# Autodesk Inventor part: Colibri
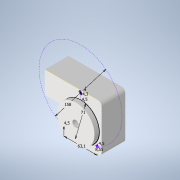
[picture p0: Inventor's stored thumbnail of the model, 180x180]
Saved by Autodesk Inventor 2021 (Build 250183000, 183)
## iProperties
Created: 2021-03
Part Number: Colibri
Material: Genérico
Document SubType Name: Modeling
Designer: ATOUZA
Density: 1 g/cm^3
Appearance: Valor por defecto
Author: ATOUZA
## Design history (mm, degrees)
sketch "Boceto1"
  geometry: L1 (-36.9, -38.8)-(40.1, -38.8); L2 (-67.9, 51.2)-(40.1, 51.2); L3 (40.1, 51.2)-(40.1, -38.8); L4 (-36.9, -38.8)-(-36.9, 4.4); L5 (-67.9, 51.2)-(-67.9, 9.2); L6 (-67.9, 9.2)-(-40.9, 9.2); L7 (-40.9, 9.2)-(-40.9, 4.4); L8 (-40.9, 4.4)-(-36.9, 4.4); C1 r 6.4 at (0, 0); C2 r 35.5 at (0, 0); 1 further point
  constraints: 16 end point, 3 perpendicular, 2 centre point, 2 coincident, 2 horizontal, 2 vertical, 1 parallel
  dimensions: "d0" = 12.8 diameter of C1; "d1" = 71 diameter of C2; "d2" = 38.8 distance from line of L1 C2.centre; "d3" = 90 distance between parallel lines of L2 L1; "d4" = 51.2 distance from line of L2 C2.centre (derived); "d5" = 40.1 distance from line of L3 C2.centre; "d6" = 77 distance of L1.start L1.end; "d7" = 108 distance of L2.start L2.end; "d8" = 42 distance of L2.start L5.end; "d9" = 27 distance of L5.end L6.end; "d10" = 4.8 distance of L6.end L7.end
extrude "Extrusión1" new body sketch "Boceto1" distance "d11" = 45; taper "d12" = 0 deg
fillet "Empalme1" dims "d13" = 7
sketch "Boceto2"
  geometry: L1 (33.1, 51.2)-(-67.9, 51.2) reference; L2 (0, 51.2)-(0, -38.8); L3 (-29.9, -38.8)-(33.1, -38.8) reference; L4 (40.1, -31.8)-(40.1, 44.2) reference; C1 r 6.4 at (0, 0) reference; C2 r 35.5 at (0, 0); C3 r 2.25 at (0, 46.9); C4 r 2.25 at (31.55, -25.526); C5 r 2.25 at (-31.55, -25.526); A1 r 79 centre (0, 46.9) between (31.55, -25.526) and (-31.55, -25.526); 3 further points
  constraints: 6 coincident, 5 centre point, 3 point on line, 2 end point, 2 point on circle, 1 vertical
  dimensions: "d14" = 71 diameter of C2; "d15" = 4.3 distance from line of point (0, 46.9) L1; "d16" = 158 diameter of A1; "d17" = 8.55 distance from line of A1.start L4; "d18" = 63.1 distance of A1.start A1.end; "d19" = 4.5 diameter of C3; "d20" = 4.5 diameter of C4; "d21" = 4.5 diameter of C5
extrude "Extrusión2" join sketch "Boceto2" distance "d22" = 9; taper "d23" = 0 deg
hole "Agujero1" sketch "Boceto2" diameter "d24" = 4.5; stored, may be unused: countersink angle "d28" = 90 deg, drill point angle "d30" = 118 deg; dims "d25" = 6, "d26" = 4, "d27" = 2, "d29" = 8
node "Sólido1"
